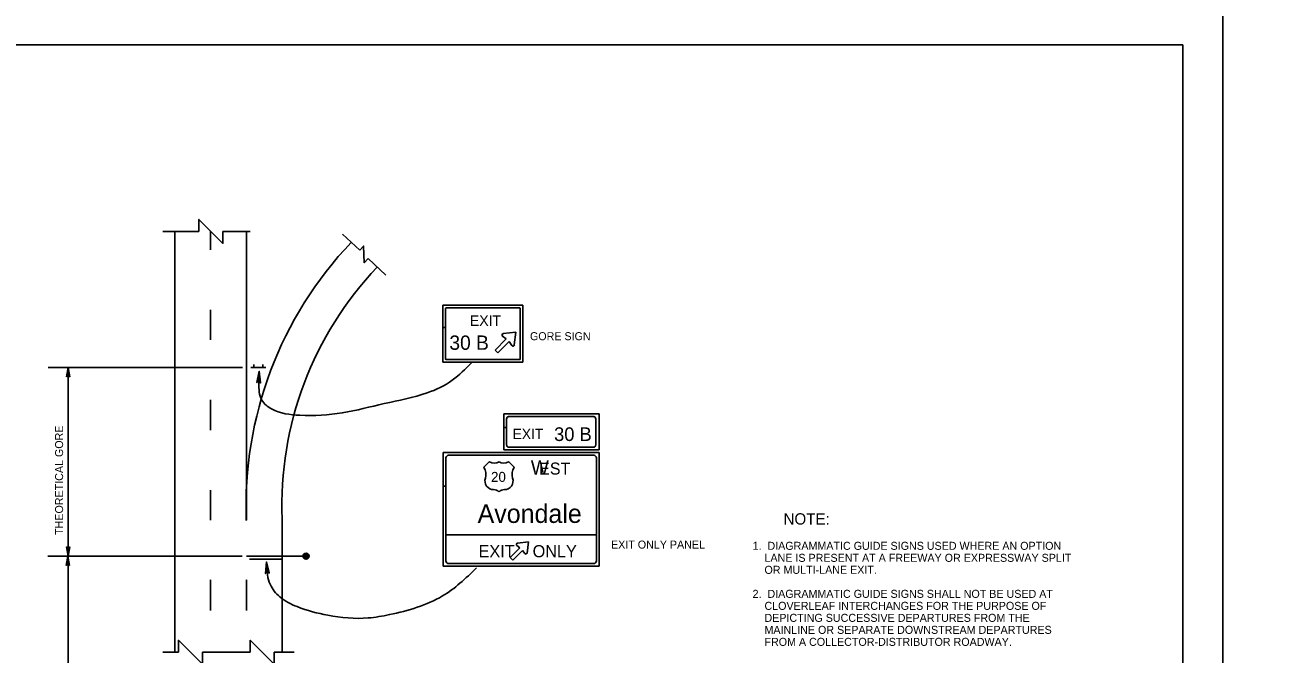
# Model space of a CAD drawing. Extents: x 644898 to 648326, y 298294 to 300670.
# Drawn here: x 645290.3 to 645756.3, y 299239.1 to 299475 of the extents above; entities that cross this region are included whole.
import ezdxf

# ---------------------------------------------------------------- set-up
doc = ezdxf.new("R2010")
doc.units = 0
for name, color, linetype in [('1', 7, 'Continuous'), ('2', 7, 'Continuous'), ('XCS-GRID-MIN', 7, 'Continuous')]:
    doc.layers.add(name, color=color, linetype=linetype)

msp = doc.modelspace()

# ---------------------------------------------------------------- linework, layer by layer
at = {"layer": '1'}
for p in [(644938.32, 299467.49), (645724.32, 298903.49)]:
    msp.add_line(p, (645724.32, 299467.49), dxfattribs=at)
at = {"layer": '2'}
for p, q in [((645342.04, 299397.54), (645355.54, 299397.54)), ((645346.54, 299239.79), (645346.54, 299397.54)), ((645359.91, 299390.67), (645359.91, 299397.67)), ((645364.54, 299397.54), (645374.79, 299397.54)), ((645373.41, 299295.79), (645373.41, 299397.54)), ((645409.41, 299396.54), (645415.91, 299390.54)), ((645359.91, 299390.67), (645359.91, 299390.67)), ((645419.04, 299387.42), (645425.66, 299381.17)), ((645359.91, 299368.17), (645359.91, 299368.17)), ((645359.91, 299356.92), (645359.91, 299368.17)), ((645477.04, 299369.92), (645447.04, 299369.92)), ((645447.04, 299369.92), (645447.04, 299361.5)), ((645448.04, 299361.5), (645448.04, 299368.67)), ((645448.29, 299368.92), (645475.79, 299368.92)), ((645476.04, 299368.67), (645476.04, 299349.79)), ((645477.04, 299348.54), (645477.04, 299369.92)), ((645359.91, 299356.92), (645359.91, 299356.92)), ((645448.04, 299361.5), (645447.04, 299361.5)), ((645447.04, 299361.5), (645447.04, 299348.54)), ((645447.04, 299361.5), (645448.04, 299361.5)), ((645448.04, 299349.79), (645448.04, 299361.5)), ((645466.64, 299353.11), (645470.77, 299357.24)), ((645470.77, 299357.24), (645469.39, 299358.24)), ((645469.64, 299359.24), (645474.39, 299359.86)), ((645474.39, 299359.86), (645473.77, 299355.11)), ((645467.64, 299351.99), (645466.64, 299353.11)), ((645471.89, 299356.24), (645467.64, 299351.99)), ((645472.89, 299354.74), (645471.89, 299356.24)), ((645376.16, 299346.54), (645376.16, 299347.67)), ((645379.54, 299346.54), (645379.54, 299347.67)), ((645447.04, 299348.54), (645477.04, 299348.54)), ((645475.79, 299349.54), (645448.29, 299349.54)), ((645371.91, 299346.54), (645299.04, 299346.54)), ((645305.91, 299343.04), (645306.54, 299346.54)), ((645306.04, 299343.17), (645305.91, 299343.04)), ((645306.54, 299346.54), (645306.04, 299343.17)), ((645306.04, 299343.17), (645306.29, 299343.29)), ((645306.29, 299343.29), (645306.54, 299346.54)), ((645306.54, 299346.54), (645306.54, 299275.79)), ((645306.54, 299346.54), (645306.66, 299343.29)), ((645306.91, 299343.17), (645306.54, 299346.54)), ((645306.54, 299346.54), (645307.16, 299343.04)), ((645306.66, 299343.29), (645306.91, 299343.17)), ((645307.16, 299343.04), (645306.91, 299343.17)), ((645380.66, 299346.54), (645375.04, 299346.54)), ((645359.91, 299334.42), (645359.91, 299334.42)), ((645359.91, 299323.04), (645359.91, 299334.42)), ((645469.91, 299324.12), (645469.91, 299329.17)), ((645469.91, 299329.17), (645505.54, 299329.17)), ((645505.54, 299329.17), (645505.54, 299315.67)), ((645470.91, 299327.42), (645470.91, 299324.12)), ((645503.66, 299328.17), (645471.54, 299328.17)), ((645504.29, 299317.42), (645504.29, 299327.42)), ((645359.91, 299323.04), (645359.91, 299323.04)), ((645470.91, 299324.12), (645469.91, 299324.12)), ((645469.91, 299315.67), (645469.91, 299324.12)), ((645469.91, 299324.12), (645470.91, 299324.12)), ((645470.91, 299324.12), (645470.91, 299317.42)), ((645505.54, 299315.67), (645469.91, 299315.67)), ((645471.54, 299316.67), (645503.66, 299316.67)), ((645447.16, 299302.07), (645447.16, 299314.67)), ((645447.16, 299314.67), (645505.54, 299314.67)), ((645503.54, 299313.67), (645449.16, 299313.67)), ((645462.3, 299309.04), (645464.55, 299311.29)), ((645471.67, 299311.29), (645473.8, 299309.04)), ((645504.54, 299274.04), (645504.54, 299312.67)), ((645505.54, 299314.67), (645505.54, 299272.04)), ((645448.16, 299302.07), (645447.16, 299302.07)), ((645447.16, 299272.04), (645447.16, 299302.07)), ((645447.16, 299302.07), (645448.16, 299302.07)), ((645468.05, 299305.54), (645468.05, 299305.54)), ((645468.05, 299305.54), (645468.05, 299305.54)), ((645468.05, 299305.54), (645468.05, 299305.54)), ((645468.05, 299305.54), (645468.05, 299305.54)), ((645468.05, 299305.54), (645468.05, 299305.54)), ((645468.05, 299305.54), (645468.05, 299305.54)), ((645470.3, 299303.29), (645470.3, 299303.29)), ((645473.3, 299304.04), (645473.3, 299304.04)), ((645359.91, 299300.54), (645359.91, 299300.54)), ((645359.91, 299289.29), (645359.91, 299300.54)), ((645373.41, 299300.54), (645373.41, 299300.54)), ((645373.41, 299289.29), (645373.41, 299300.54)), ((645466.05, 299300.79), (645466.05, 299300.79)), ((645470.05, 299300.79), (645470.05, 299300.79)), ((645359.91, 299289.29), (645359.91, 299289.29)), ((645373.41, 299289.29), (645373.41, 299289.29)), ((645386.79, 299239.79), (645386.79, 299289.79)), ((645306.54, 299275.79), (645305.91, 299279.29)), ((645305.91, 299279.29), (645306.16, 299279.17)), ((645306.41, 299279.04), (645306.16, 299279.17)), ((645306.16, 299279.17), (645306.54, 299275.79)), ((645306.54, 299275.79), (645306.41, 299279.04)), ((645307.16, 299279.29), (645306.54, 299275.79)), ((645306.54, 299275.79), (645307.04, 299279.17)), ((645306.79, 299279.04), (645306.54, 299275.79)), ((645307.04, 299279.17), (645306.79, 299279.04)), ((645307.04, 299279.17), (645307.16, 299279.29)), ((645475.9, 299279), (645472.21, 299275.38)), ((645473.21, 299274.38), (645476.84, 299278)), ((645474.71, 299279.82), (645475.9, 299279)), ((645479.09, 299281.25), (645474.96, 299280.75)), ((645476.84, 299278), (645477.71, 299276.82)), ((645478.59, 299277), (645479.09, 299281.25)), ((645371.79, 299275.79), (645298.91, 299275.79)), ((645305.79, 299272.29), (645306.41, 299275.79)), ((645306.41, 299275.79), (645305.91, 299272.42)), ((645306.16, 299272.54), (645306.41, 299275.79)), ((645306.41, 299275.79), (645306.54, 299272.54)), ((645306.79, 299272.42), (645306.41, 299275.79)), ((645306.41, 299275.79), (645307.04, 299272.29)), ((645306.54, 299275.79), (645306.54, 299177.29)), ((645373.41, 299275.79), (645395.79, 299275.79)), ((645374.54, 299274.67), (645386.79, 299274.67)), ((645394.79, 299275.67), (645395.91, 299276.79)), ((645396.54, 299276.29), (645394.79, 299275.67)), ((645395.91, 299276.79), (645394.91, 299276.42)), ((645395.04, 299275.17), (645395.04, 299276.29)), ((645395.04, 299276.29), (645395.41, 299275.04)), ((645395.41, 299275.04), (645395.54, 299276.54)), ((645395.54, 299276.54), (645395.91, 299274.92)), ((645395.66, 299274.92), (645396.54, 299276.29)), ((645396.54, 299275.67), (645395.66, 299274.92)), ((645395.79, 299275.79), (645395.79, 299275.79)), ((645395.91, 299274.92), (645395.91, 299276.79)), ((645395.91, 299276.79), (645396.29, 299275.17)), ((645396.29, 299275.17), (645396.29, 299276.54)), ((645396.29, 299276.54), (645396.54, 299275.67)), ((645449.16, 299273.04), (645503.54, 299273.04)), ((645472.21, 299275.38), (645473.21, 299274.38)), ((645305.91, 299272.42), (645305.79, 299272.29)), ((645305.91, 299272.42), (645306.16, 299272.54)), ((645306.54, 299272.54), (645306.79, 299272.42)), ((645307.04, 299272.29), (645306.79, 299272.42)), ((645505.54, 299272.04), (645447.16, 299272.04)), ((645359.91, 299267.04), (645359.91, 299267.04)), ((645359.91, 299266.92), (645359.91, 299266.92)), ((645359.91, 299255.42), (645359.91, 299266.92)), ((645373.41, 299267.04), (645373.41, 299267.04)), ((645373.41, 299266.92), (645373.41, 299266.92)), ((645373.41, 299255.42), (645373.41, 299266.92)), ((645359.91, 299255.67), (645359.91, 299255.67)), ((645359.91, 299255.42), (645359.91, 299255.42)), ((645373.41, 299255.67), (645373.41, 299255.67)), ((645373.41, 299255.42), (645373.41, 299255.42)), ((645342.04, 299239.79), (645347.91, 299239.79)), ((645356.91, 299239.79), (645374.79, 299239.79)), ((645383.79, 299239.79), (645391.29, 299239.79))]:
    msp.add_line(p, q, dxfattribs=at)
for points in [[(645355.54, 299397.54), (645355.54, 299402.04), (645364.54, 299393.04), (645364.54, 299397.54)], [(645415.91, 299390.54), (645417.29, 299392.04), (645417.54, 299385.79), (645419.04, 299387.42)], [(645377.54, 299341.17), (645377.79, 299341.29), (645378.16, 299345.17), (645377.54, 299341.17), (645377.29, 299340.92), (645378.16, 299345.17), (645378.29, 299341.29), (645378.54, 299341.17), (645378.16, 299345.17), (645378.66, 299340.79), (645378.54, 299341.17)], [(645448.16, 299312.67), (645448.16, 299302.07)], [(645448.16, 299302.07), (645448.16, 299274.04)], [(645448.16, 299283.79), (645504.54, 299283.79)], [(645380.79, 299269.54), (645380.91, 299269.67), (645380.91, 299273.67), (645380.79, 299269.54), (645380.54, 299269.29), (645380.91, 299273.67), (645381.41, 299269.79), (645381.66, 299269.67), (645380.91, 299273.67), (645381.91, 299269.54), (645381.66, 299269.67)], [(645347.91, 299239.79), (645347.91, 299244.29), (645356.91, 299235.29), (645356.91, 299239.79)], [(645374.79, 299239.79), (645374.79, 299244.29), (645383.79, 299235.29), (645383.79, 299239.79)]]:
    msp.add_lwpolyline(points, dxfattribs=at)
msp.add_circle((645395.72, 299275.82), 1.12, dxfattribs=at)
for centre, radius, start, end in [((645516.36, 299294.78), 143.14, 136.4155, 182.2116), ((645516.36, 299294.78), 129.7, 136.4155, 182.2116), ((645448.29, 299368.67), 0.25, 90, 180), ((645475.79, 299368.67), 0.25, 0, 90), ((645469.77, 299358.69), 0.559, 94.8591, 235.5247), ((645473.32, 299355.09), 0.559, 213.2476, 357.1543), ((645448.29, 299349.79), 0.25, 180, 270), ((645475.79, 299349.79), 0.25, 270, 360), ((645449.16, 299312.67), 1, 90, 180), ((645466.3, 299313.59), 2.93, 233.136, 306.864), ((645469.81, 299313.59), 2.93, 233.136, 306.864), ((645503.54, 299312.67), 1, 0, 90), ((645458.63, 299306.49), 4.55, 341.8289, 34.5747), ((645477.47, 299306.49), 4.55, 145.4253, 198.1711), ((645466.05, 299304.03), 3.26, 161.452, 269.9953), ((645470.06, 299304.03), 3.26, 270.0047, 18.548), ((645466.04, 299298.01), 2.76, 43.7275, 90), ((645470.06, 299298.01), 2.76, 90, 136.2725), ((645475.01, 299280.25), 0.489, 94.8565, 235.522), ((645449.16, 299274.04), 1, 180, 270), ((645478.12, 299277.1), 0.489, 213.2449, 357.1516), ((645503.54, 299274.04), 1, 270, 360)]:
    msp.add_arc(centre, radius, start, end, dxfattribs=at)
for centre, major_axis, start_param, end_param in [((645471.59, 299327.32), (0, -0.792), 3.141593, 4.712389), ((645503.62, 299327.32), (0, 0.792), 4.712389, 6.283185), ((645471.59, 299317.47), (0, -0.792), 4.712389, 6.283185), ((645503.62, 299317.47), (0, 0.792), 3.141593, 4.712389)]:
    msp.add_ellipse(centre, major_axis=major_axis, ratio=0.827467, start_param=start_param, end_param=end_param, dxfattribs=at)
for points in [[(645378.16, 299345.17), (645378.04, 299340.79), (645379.16, 299334.29), (645382.79, 299331.04), (645393.41, 299328.67), (645409.29, 299329.54), (645425.04, 299333.04), (645441.16, 299337.04), (645450.54, 299341.79), (645457.79, 299348.29)], [(645380.91, 299273.67), (645381.29, 299268.79), (645382.29, 299265.29), (645385.91, 299260.54), (645392.41, 299256.92), (645403.91, 299253.67), (645419.04, 299252.67), (645427.04, 299253.92), (645437.41, 299256.67), (645446.91, 299260.92), (645453.41, 299265.67), (645459.66, 299271.42)]]:
    msp.add_spline(points, degree=3, dxfattribs=at)
at = {"layer": 'XCS-GRID-MIN'}
for points in [[(644898.32, 299482.49), (645739.32, 299482.49), (645739.32, 298888.49), (644898.32, 298888.49)], [(645739.32, 299482.49), (646580.32, 299482.49), (646580.32, 298888.49), (645739.32, 298888.49)]]:
    msp.add_lwpolyline(points, close=True, dxfattribs=at)

# ---------------------------------------------------------------- texts
at = {"layer": '2'}
for s, height, p in [('EXIT', 3.917, (645457.16, 299362.17)), ('30 B ', 5.375, (645449.46, 299353.18)), ('GORE SIGN', 3, (645479.66, 299356.79)), ('EXIT', 3.875, (645473.15, 299319.71)), ('30 B', 5.125, (645488.71, 299319)), ('W', 5.38, (645479.96, 299306.42)), ('EST', 4.5, (645483.08, 299306.42)), ('20', 3.75, (645465.05, 299303.67)), ('NOTE:', 4.25, (645574.68, 299287.67)), ('EXIT    ONLY', 4.5457, (645460.4, 299275.42)), ('EXIT ONLY PANEL', 3, (645510.04, 299278.67)), ('1.  DIAGRAMMATIC GUIDE SIGNS USED WHERE AN OPTION ', 3, (645563.1, 299278.21)), ('    LANE IS PRESENT AT A FREEWAY OR EXPRESSWAY SPLIT ', 3, (645563.1, 299273.71)), ('    OR MULTI-LANE EXIT.', 3, (645563.1, 299269.21)), ('2.  DIAGRAMMATIC GUIDE SIGNS SHALL NOT BE USED AT ', 3, (645563.1, 299260.21)), ('    CLOVERLEAF INTERCHANGES FOR THE PURPOSE OF ', 3, (645563.1, 299255.71)), ('    DEPICTING SUCCESSIVE DEPARTURES FROM THE ', 3, (645563.1, 299251.21)), ('    MAINLINE OR SEPARATE DOWNSTREAM DEPARTURES', 3, (645563.1, 299246.71)), ('    FROM A COLLECTOR-DISTRIBUTOR ROADWAY. ', 3, (645563.1, 299242.21))]:
    msp.add_text(s, height=height, dxfattribs=at).set_placement(p)
for s, height, rotation, p in [('THEORETICAL GORE', 3, 90, (645304.66, 299283.79)), ('Avondale', 7, 359.9998, (645460.03, 299288.29))]:
    msp.add_text(s, height=height, rotation=rotation, dxfattribs=at).set_placement(p)

doc.saveas('drawing.dxf')
